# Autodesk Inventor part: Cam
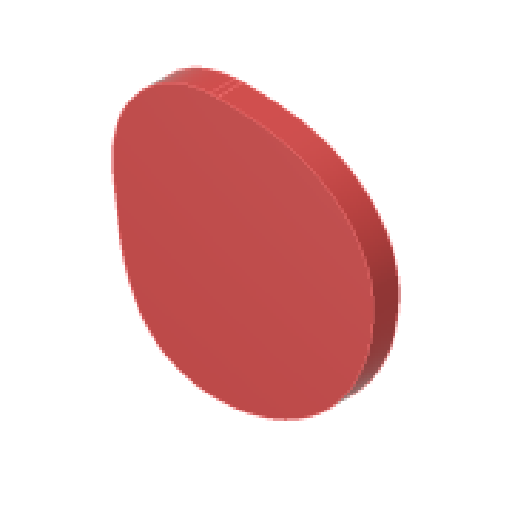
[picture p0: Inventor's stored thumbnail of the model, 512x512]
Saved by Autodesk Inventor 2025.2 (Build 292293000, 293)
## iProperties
Created: 2024-10
Part Number: Cam
Material: Generic
Document SubType Name: Modeling
Designer: Dennis
Mass: 81.1794 g
Surface Area: 195.908 cm^2
Volume: 81.1794 cm^3
Density: 1 g/cm^3
Appearance: Smooth - Red
Author: Dennis
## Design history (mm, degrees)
sketch "Sketch1"
  geometry: C1 r 40 at (0, 0); 1 further point
  constraints: 1 centre point, 1 coincident
  dimensions: "d0" = 80 diameter of C1
extrude "Extrusion1" new body sketch "Sketch1" distance "d1" = 10; taper "d2" = 0 deg
sketch "Sketch3" dims "d6" = 10
  geometry: 101 further points
  constraints: 202 other
extrude "擠出4" join sketch "Sketch3" distance "d9" = 10; taper "d10" = 0 deg
sketch "草圖4"
  geometry: 1 further point
sketch "草圖5"
  geometry: C1 r 5 at (-26.312, -42.517); 1 further point
  constraints: 1 centre point, 1 coincident
  dimensions: "d11" = 10 diameter of C1
extrude "擠出5" join sketch "草圖5" distance "d12" = 10; taper "d13" = 0 deg
body "Solid1"
